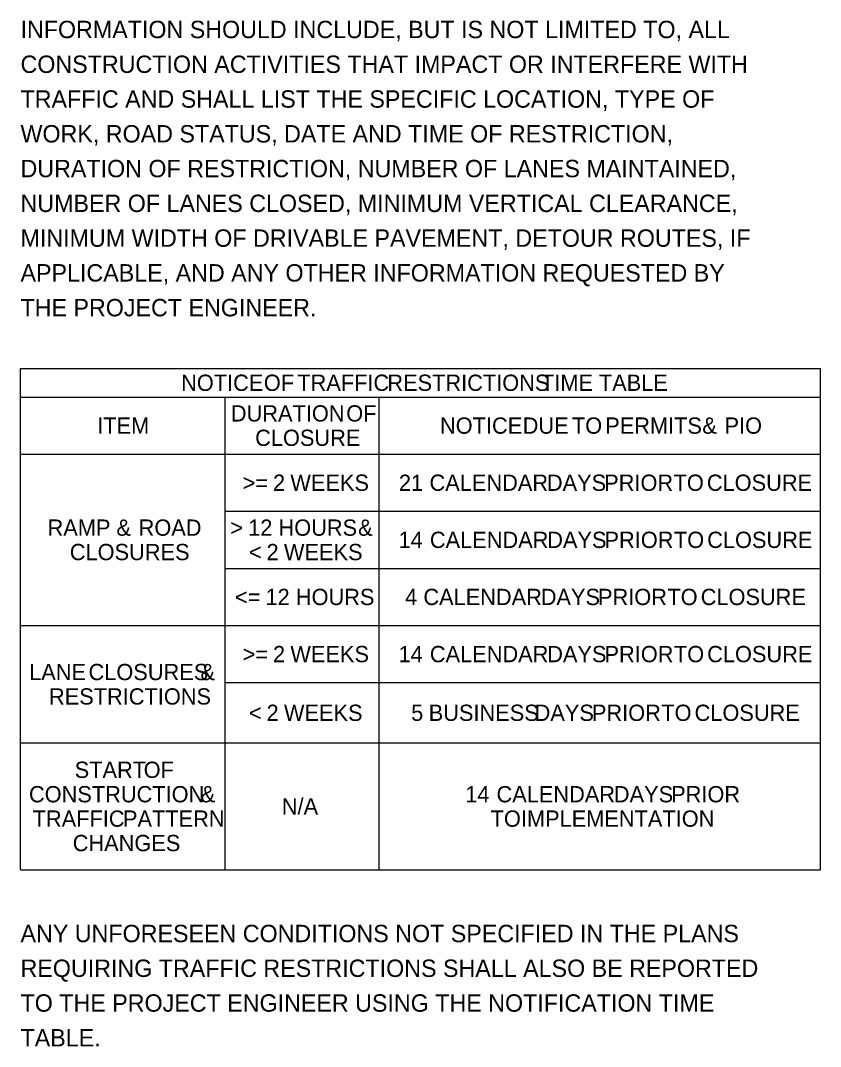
# Model space of a CAD drawing. Extents: x 0 to 83.7, y 0 to 22.
# Drawn here: x 37.32 to 43.76, y 1.8 to 10.06 of the extents above; entities that cross this region are included whole.
import ezdxf

# ---------------------------------------------------------------- set-up
doc = ezdxf.new("R2010")
doc.units = 0
doc.layers.add('Default', color=7, linetype='Continuous')
doc.layers.add('SH_Text', color=7, linetype='Continuous')

msp = doc.modelspace()

# ---------------------------------------------------------------- linework, layer by layer
at = {"layer": 'Default'}
for p, q in [((37.3174, 7.2581), (43.7574, 7.2581)), ((37.3174, 3.2203), (37.3174, 7.2581)), ((43.7574, 3.2203), (43.7574, 7.2581)), ((37.3174, 7.0281), (43.7574, 7.0281)), ((38.9658, 3.2203), (38.9658, 7.0281)), ((40.2052, 3.2203), (40.2052, 7.0281)), ((37.3174, 6.5681), (43.7574, 6.5681)), ((38.9658, 6.1081), (43.7574, 6.1081)), ((38.9658, 5.6481), (43.7574, 5.6481)), ((37.3174, 5.1881), (43.7574, 5.1881)), ((38.9658, 4.7281), (43.7574, 4.7281)), ((37.3174, 4.2425), (43.7574, 4.2425)), ((37.3174, 3.2203), (43.7574, 3.2203))]:
    msp.add_line(p, q, dxfattribs=at)
at = {"layer": 'SH_Text'}
msp.add_line((37.3174, 7.2581), (37.3174, 7.2581), dxfattribs=at)

# ---------------------------------------------------------------- texts
at = {"layer": 'Default'}
for s, height, p in [('NOTICE', 0.13105, (38.6103, 7.0776)), (' OF', 0.13105, (39.2275, 7.0776)), (' TRAFFIC', 0.13105, (39.4968, 7.0776)), (' RESTRICTIONS', 0.131054, (40.2219, 7.0776)), (' TIME', 0.13105, (41.459, 7.0776)), (' TABLE', 0.13105, (41.9249, 7.0776)), ('DURATION', 0.13105, (39.0107, 6.8309)), (' OF', 0.13105, (39.8911, 6.8309)), ('ITEM', 0.13105, (37.9353, 6.7326)), ('NOTICE', 0.13105, (40.6943, 6.7326)), (' DUE', 0.13105, (41.3115, 6.7326)), (' TO', 0.13105, (41.7077, 6.7326)), (' PERMITS', 0.13105, (41.9757, 6.7326)), (' &', 0.13105, (42.7576, 6.7326)), (' PIO', 0.13105, (42.9364, 6.7326)), ('CLOSURE', 0.13105, (39.2062, 6.6343)), ('>=', 0.13105, (39.1052, 6.2726)), (' 2', 0.13105, (39.3013, 6.2726)), (' WEEKS', 0.13105, (39.4411, 6.2726)), ('21', 0.13105, (40.3635, 6.2726)), (' CALENDAR', 0.13105, (40.5615, 6.2726)), (' DAYS', 0.13105, (41.5063, 6.2726)), (' PRIOR', 0.13105, (41.9675, 6.2726)), (' TO', 0.13105, (42.526, 6.2726)), (' CLOSURE', 0.13105, (42.7941, 6.2726)), ('RAMP', 0.13105, (37.5353, 5.9109)), (' &', 0.13105, (38.0409, 5.9109)), (' ROAD', 0.13105, (38.2197, 5.9109)), (' 12', 0.13105, (39.1013, 5.9109)), (' HOURS', 0.13105, (39.3457, 5.9109)), (' &', 0.13105, (39.9869, 5.9109)), ('>', 0.1311, (39.0053, 5.9109)), ('14', 0.13105, (40.3608, 5.8126)), (' CALENDAR', 0.13105, (40.5641, 5.8126)), (' DAYS', 0.13105, (41.5089, 5.8126)), (' PRIOR', 0.13105, (41.9701, 5.8126)), (' TO', 0.13105, (42.5287, 5.8126)), (' CLOSURE', 0.13105, (42.7967, 5.8126)), ('CLOSURES', 0.13105, (37.7142, 5.7143)), ('<', 0.1311, (39.1569, 5.7143)), (' 2', 0.13105, (39.2496, 5.7143)), (' WEEKS', 0.13105, (39.3894, 5.7143)), ('<=', 0.13105, (39.0446, 5.3526)), (' 12', 0.13105, (39.2408, 5.3526)), (' HOURS', 0.13105, (39.4852, 5.3526)), ('4', 0.1311, (40.4131, 5.3526)), (' CALENDAR', 0.13105, (40.5118, 5.3526)), (' DAYS', 0.13105, (41.4566, 5.3526)), (' PRIOR', 0.13105, (41.9178, 5.3526)), (' TO', 0.13105, (42.4764, 5.3526)), (' CLOSURE', 0.13105, (42.7444, 5.3526)), ('>=', 0.13105, (39.1052, 4.8926)), (' 2', 0.13105, (39.3013, 4.8926)), (' WEEKS', 0.13105, (39.4411, 4.8926)), ('14', 0.13105, (40.3608, 4.8926)), (' CALENDAR', 0.13105, (40.5641, 4.8926)), (' DAYS', 0.13105, (41.5089, 4.8926)), (' PRIOR', 0.13105, (41.9701, 4.8926)), (' TO', 0.13105, (42.5287, 4.8926)), (' CLOSURE', 0.13105, (42.7967, 4.8926)), ('LANE', 0.13105, (37.3868, 4.7481)), (' CLOSURES', 0.13105, (37.8163, 4.7481)), (' &', 0.13105, (38.7176, 4.7481)), ('RESTRICTIONS', 0.131054, (37.5464, 4.5515)), (' 2', 0.13105, (39.2496, 4.4198)), (' WEEKS', 0.13105, (39.3894, 4.4198)), ('5', 0.1311, (40.4622, 4.4198)), (' BUSINESS', 0.13105, (40.5548, 4.4198)), (' DAYS', 0.13105, (41.4075, 4.4198)), (' PRIOR', 0.13105, (41.8687, 4.4198)), (' TO', 0.13105, (42.4273, 4.4198)), (' CLOSURE', 0.13105, (42.6953, 4.4198)), ('<', 0.1311, (39.1569, 4.4198)), ('START', 0.13105, (37.7536, 3.9608)), (' OF', 0.13105, (38.2604, 3.9608)), ('CONSTRUCTION', 0.131054, (37.3854, 3.7642)), (' &', 0.13105, (38.719, 3.7642)), ('14', 0.13105, (40.8974, 3.7642)), (' CALENDAR', 0.13105, (41.1007, 3.7642)), (' DAYS', 0.13105, (42.0455, 3.7642)), (' PRIOR', 0.13105, (42.5067, 3.7642)), ('N/A', 0.13105, (39.421, 3.6659)), ('TRAFFIC', 0.13105, (37.4152, 3.5676)), (' PATTERN', 0.13105, (38.0937, 3.5676)), ('TOIMPLEMENTATION', 0.131054, (41.1022, 3.5676)), ('CHANGES', 0.13105, (37.7376, 3.371))]:
    msp.add_text(s, height=height, dxfattribs=at).set_placement(p)
at = {"layer": 'SH_Text'}
for s, p in [('INFORMATION SHOULD INCLUDE, BUT IS NOT LIMITED TO, ALL', (37.3174, 9.9181)), ('CONSTRUCTION ACTIVITIES THAT IMPACT OR INTERFERE WITH', (37.3174, 9.6381)), ('TRAFFIC AND SHALL LIST THE SPECIFIC LOCATION, TYPE OF', (37.3174, 9.3581)), ('WORK, ROAD STATUS, DATE AND TIME OF RESTRICTION,', (37.3174, 9.0781)), ('DURATION OF RESTRICTION, NUMBER OF LANES MAINTAINED,', (37.3174, 8.7981)), ('NUMBER OF LANES CLOSED, MINIMUM VERTICAL CLEARANCE,', (37.3174, 8.5181)), ('MINIMUM WIDTH OF DRIVABLE PAVEMENT, DETOUR ROUTES, IF', (37.3174, 8.2381)), ('APPLICABLE, AND ANY OTHER INFORMATION REQUESTED BY', (37.3174, 7.9581)), ('THE PROJECT ENGINEER.', (37.3174, 7.6781)), ('ANY UNFORESEEN CONDITIONS NOT SPECIFIED IN THE PLANS', (37.3174, 2.6381)), ('REQUIRING TRAFFIC RESTRICTIONS SHALL ALSO BE REPORTED', (37.3174, 2.3581)), ('TO THE PROJECT ENGINEER USING THE NOTIFICATION TIME', (37.3174, 2.0781)), ('TABLE.', (37.3174, 1.7981))]:
    msp.add_text(s, height=0.14, dxfattribs=at).set_placement(p)

doc.saveas('drawing.dxf')
